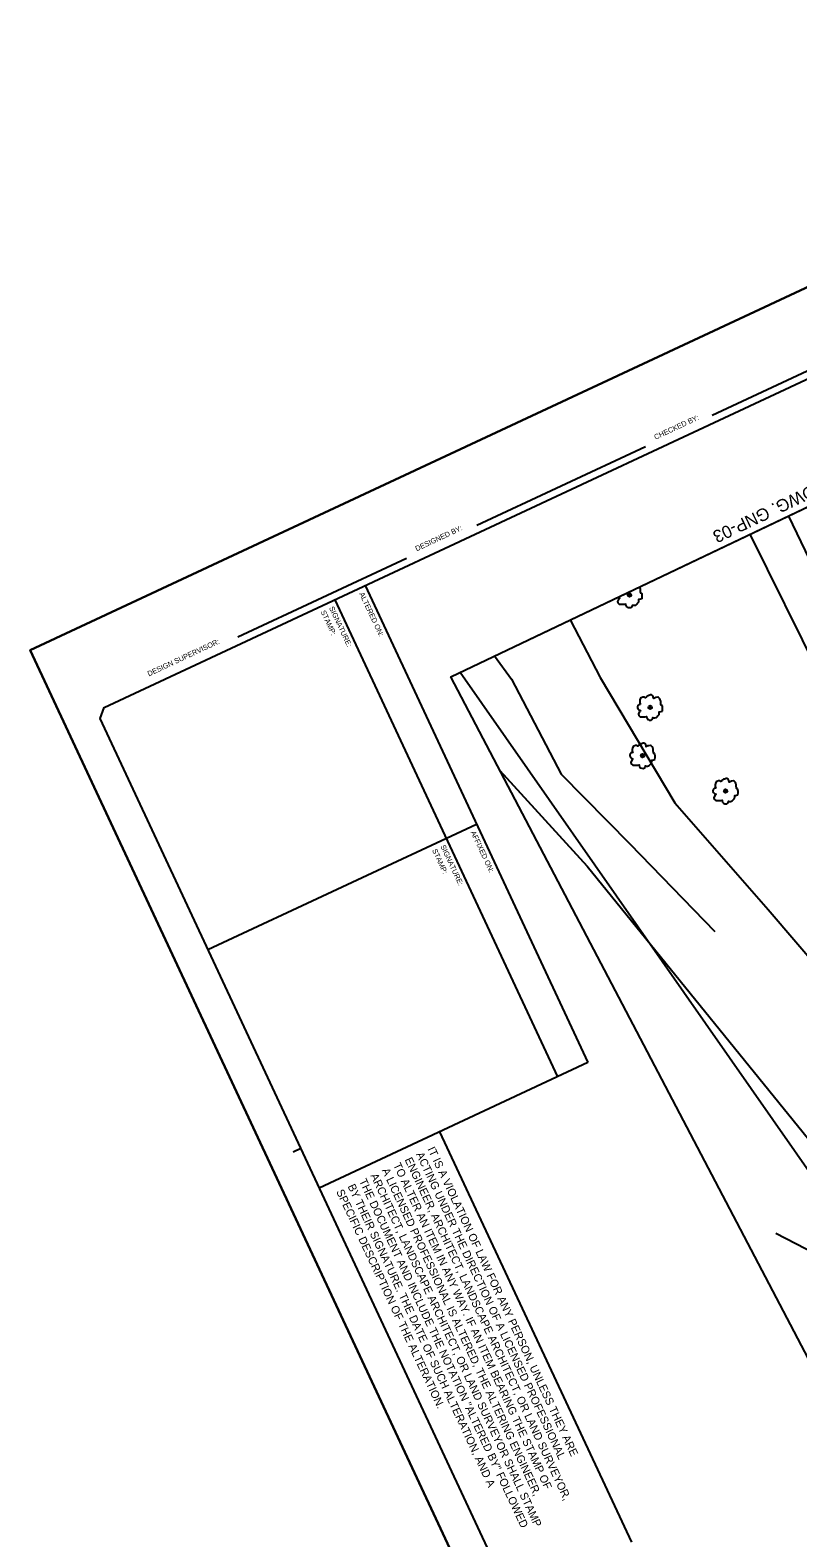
# Model space of a CAD drawing. Extents: x 1040814 to 1041501, y 1126274 to 1127077.
# Drawn here: x 1040814.3 to 1041044.8, y 1126623.9 to 1127076.7 of the extents above; entities that cross this region are included whole.
import ezdxf

# ---------------------------------------------------------------- set-up
doc = ezdxf.new("R2010")
doc.units = 0
for name, color, linetype in [('clip boundary', 7, 'Continuous'), ('LAM', 7, 'Continuous'), ('LAWA', 7, 'Continuous'), ('LELB', 7, 'Continuous'), ('LTD', 7, 'Continuous'), ('MHB', 7, 'Continuous'), ('NML_P', 7, 'Continuous'), ('NML_P_T', 7, 'Continuous'), ('SHEET_BORDER', 7, 'Continuous'), ('SHEET_BORDER_CUT', 7, 'Continuous'), ('SHEET_BORDER_STAMPBOX', 7, 'Continuous'), ('SHEET_BORDER_TEXT', 7, 'Continuous')]:
    doc.layers.add(name, color=color, linetype=linetype)

msp = doc.modelspace()

# ---------------------------------------------------------------- linework, layer by layer
at = {"layer": 'clip boundary'}
for points in [[(1041212.91, 1127076.67), (1041500.71, 1126460.57), (1041102.06, 1126274.35), (1040814.26, 1126890.45)], [(1041214.88, 1127013.05), (1041436.47, 1126509.64), (1041196.3, 1126394.87), (1040940.57, 1126882.48)]]:
    msp.add_lwpolyline(points, close=True, dxfattribs=at)
at = {"layer": 'LAM'}
msp.add_lwpolyline([(1040981.59, 1126825.54), (1040955.31, 1126854.36)], dxfattribs=at)
at = {"layer": 'LAWA'}
for points in [[(1040955.31, 1126854.36), (1040981.59, 1126825.54)], [(1040981.59, 1126825.54), (1041056.77, 1126732.84), (1041104.86, 1126716.99), (1041144.53, 1126704.03), (1041174.4, 1126657.67), (1041200.18, 1126609.9)]]:
    msp.add_lwpolyline(points, dxfattribs=at)
at = {"layer": 'LELB'}
for points in [[(1041041.98, 1126930.75), (1041063.24, 1126886.6), (1041084.03, 1126841.27), (1041108.41, 1126799.02), (1041128.47, 1126753.39), (1041143.12, 1126720.8)], [(1041123.26, 1126726.85), (1041116.78, 1126745.76), (1041096.43, 1126789.68), (1041075.03, 1126831.81), (1041051.47, 1126883.04), (1041030.52, 1126925.29)], [(1040976.45, 1126899.56), (1040985.45, 1126882.27), (1041007.93, 1126844.63)], [(1040953.75, 1126888.75), (1040958.86, 1126881.74), (1040973.79, 1126853.17), (1040994.35, 1126832.28)], [(1041007.93, 1126844.63), (1041035.89, 1126812.55)], [(1040994.35, 1126832.28), (1041019.85, 1126805.94)], [(1041035.89, 1126812.55), (1041051.97, 1126793.82)], [(1041085.87, 1126690.6), (1041038.19, 1126715.23)]]:
    msp.add_lwpolyline(points, dxfattribs=at)
at = {"layer": 'LTD'}
for points in [[(1040997.24, 1126909.45), (1040997.31, 1126909.3), (1040997.43, 1126908.91), (1040997.43, 1126908.35), (1040997.49, 1126907.93), (1040997.46, 1126907.84), (1040997.55, 1126907.72), (1040997.82, 1126907.62)], [(1040997.94, 1126905.85), (1040997.19, 1126905.69), (1040996.98, 1126905.66), (1040997.01, 1126905.22), (1040996.92, 1126904.89), (1040996.8, 1126904.71), (1040996.57, 1126904.44), (1040996.48, 1126904.32), (1040996.18, 1126904.01), (1040996.06, 1126903.92), (1040995.7, 1126903.83), (1040995.27, 1126903.89), (1040995.09, 1126903.92), (1040995.06, 1126903.77), (1040994.91, 1126903.38), (1040994.61, 1126903.2), (1040994.39, 1126903.17), (1040993.97, 1126903.2), (1040993.64, 1126903.32), (1040993.46, 1126903.44), (1040993.34, 1126903.65), (1040993.19, 1126904.07), (1040993.19, 1126904.28), (1040992.78, 1126904.16), (1040992.23, 1126904.13), (1040991.6, 1126904.13), (1040991.3, 1126904.16), (1040990.84, 1126904.53), (1040990.72, 1126905.07), (1040991.08, 1126905.72), (1040991.21, 1126905.9), (1040991.36, 1126906.08), (1040991.14, 1126906.14), (1040990.9, 1126906.27), (1040990.79, 1126906.38)], [(1040994.29, 1126907.02), (1040994.29, 1126907.02), (1040994.29, 1126907.02), (1040994.29, 1126907.04), (1040994.29, 1126907.04), (1040994.29, 1126907.04), (1040994.29, 1126907.05), (1040994.27, 1126907.05), (1040994.27, 1126907.05), (1040994.27, 1126907.05), (1040994.27, 1126907.05), (1040994.27, 1126907.07), (1040994.26, 1126907.07), (1040994.26, 1126907.07), (1040994.26, 1126907.07), (1040994.24, 1126907.07), (1040994.24, 1126907.07), (1040994.24, 1126907.07), (1040994.23, 1126907.07), (1040994.23, 1126907.07), (1040994.23, 1126907.07), (1040994.21, 1126907.07), (1040994.21, 1126907.05), (1040994.21, 1126907.05), (1040994.21, 1126907.05), (1040994.2, 1126907.05), (1040994.2, 1126907.05), (1040994.2, 1126907.04), (1040994.2, 1126907.04), (1040994.2, 1126907.04), (1040994.2, 1126907.02), (1040994.2, 1126907.02), (1040994.2, 1126907.02), (1040994.2, 1126907.01), (1040994.2, 1126907.01), (1040994.2, 1126907.01), (1040994.2, 1126906.99), (1040994.2, 1126906.99), (1040994.21, 1126906.99), (1040994.21, 1126906.99), (1040994.21, 1126906.98), (1040994.21, 1126906.98), (1040994.23, 1126906.98), (1040994.23, 1126906.98), (1040994.23, 1126906.98), (1040994.24, 1126906.98), (1040994.24, 1126906.98), (1040994.24, 1126906.98), (1040994.26, 1126906.98), (1040994.26, 1126906.98), (1040994.26, 1126906.98), (1040994.27, 1126906.98), (1040994.27, 1126906.98), (1040994.27, 1126906.99), (1040994.27, 1126906.99), (1040994.27, 1126906.99), (1040994.29, 1126906.99), (1040994.29, 1126907.01), (1040994.29, 1126907.01), (1040994.29, 1126907.01), (1040994.29, 1126907.02)], [(1040997.82, 1126907.62), (1040997.92, 1126907.32), (1040997.98, 1126906.9), (1040997.98, 1126906.42), (1040997.94, 1126905.85)], [(1040997.6, 1126874.11), (1040997.14, 1126874.17), (1040996.78, 1126873.87), (1040996.66, 1126873.47), (1040996.66, 1126873.17), (1040996.78, 1126872.87), (1040997.11, 1126872.53), (1040997.36, 1126872.41), (1040997.57, 1126872.35), (1040997.42, 1126872.17), (1040997.3, 1126871.99), (1040996.93, 1126871.34), (1040997.05, 1126870.8), (1040997.51, 1126870.43), (1040997.81, 1126870.4), (1040998.44, 1126870.4), (1040998.99, 1126870.43), (1040999.4, 1126870.55), (1040999.4, 1126870.34), (1040999.55, 1126869.92), (1040999.67, 1126869.71), (1040999.85, 1126869.59), (1041000.18, 1126869.47), (1041000.61, 1126869.44), (1041000.82, 1126869.47), (1041001.12, 1126869.65), (1041001.27, 1126870.04), (1041001.3, 1126870.19), (1041001.48, 1126870.16), (1041001.91, 1126870.1), (1041002.27, 1126870.19), (1041002.39, 1126870.28), (1041002.69, 1126870.58), (1041002.78, 1126870.71), (1041003.01, 1126870.98), (1041003.13, 1126871.16), (1041003.22, 1126871.49), (1041003.19, 1126871.93), (1041003.4, 1126871.96), (1041004.15, 1126872.12)], [(1041004.03, 1126873.89), (1041003.77, 1126873.99), (1041003.68, 1126874.11), (1041003.71, 1126874.2), (1041003.65, 1126874.62), (1041003.65, 1126875.18), (1041003.52, 1126875.57), (1041003.37, 1126875.88), (1041003.01, 1126876.24), (1041002.74, 1126876.3), (1041002.21, 1126876.24), (1041002, 1126876.18), (1041001.6, 1126875.97), (1041001.54, 1126875.94), (1041001.48, 1126876.15), (1041001.42, 1126876.48), (1041001.21, 1126876.78), (1041001, 1126876.93), (1041000.82, 1126877.02), (1041000.58, 1126877.02), (1041000.4, 1126876.93), (1041000.09, 1126876.84), (1040999.85, 1126876.78), (1040999.55, 1126876.6), (1040999.4, 1126876.42), (1040998.96, 1126876.15), (1040998.75, 1126876.33), (1040998.32, 1126876.33), (1040997.81, 1126876.15), (1040997.6, 1126876), (1040997.39, 1126875.53), (1040997.33, 1126875.07), (1040997.33, 1126874.65), (1040997.45, 1126874.35), (1040997.6, 1126874.11)], [(1041000.5, 1126873.29), (1041000.5, 1126873.29), (1041000.5, 1126873.29), (1041000.5, 1126873.31), (1041000.5, 1126873.31), (1041000.5, 1126873.31), (1041000.5, 1126873.32), (1041000.49, 1126873.32), (1041000.49, 1126873.32), (1041000.49, 1126873.32), (1041000.49, 1126873.32), (1041000.49, 1126873.34), (1041000.47, 1126873.34), (1041000.47, 1126873.34), (1041000.47, 1126873.34), (1041000.46, 1126873.34), (1041000.46, 1126873.34), (1041000.46, 1126873.34), (1041000.44, 1126873.34), (1041000.44, 1126873.34), (1041000.44, 1126873.34), (1041000.43, 1126873.34), (1041000.43, 1126873.32), (1041000.43, 1126873.32), (1041000.43, 1126873.32), (1041000.41, 1126873.32), (1041000.41, 1126873.32), (1041000.41, 1126873.31), (1041000.41, 1126873.31), (1041000.41, 1126873.31), (1041000.41, 1126873.29), (1041000.41, 1126873.29), (1041000.41, 1126873.29), (1041000.41, 1126873.28), (1041000.41, 1126873.28), (1041000.41, 1126873.28), (1041000.41, 1126873.26), (1041000.41, 1126873.26), (1041000.43, 1126873.26), (1041000.43, 1126873.26), (1041000.43, 1126873.25), (1041000.43, 1126873.25), (1041000.44, 1126873.25), (1041000.44, 1126873.25), (1041000.44, 1126873.25), (1041000.46, 1126873.25), (1041000.46, 1126873.25), (1041000.46, 1126873.25), (1041000.47, 1126873.25), (1041000.47, 1126873.25), (1041000.47, 1126873.25), (1041000.49, 1126873.25), (1041000.49, 1126873.25), (1041000.49, 1126873.26), (1041000.49, 1126873.26), (1041000.49, 1126873.26), (1041000.5, 1126873.26), (1041000.5, 1126873.28), (1041000.5, 1126873.28), (1041000.5, 1126873.28), (1041000.5, 1126873.29)], [(1041004.15, 1126872.12), (1041004.19, 1126872.69), (1041004.19, 1126873.17), (1041004.13, 1126873.59), (1041004.03, 1126873.89)], [(1040995.34, 1126859.62), (1040994.89, 1126859.68), (1040994.52, 1126859.37), (1040994.4, 1126858.98), (1040994.4, 1126858.68), (1040994.52, 1126858.38), (1040994.86, 1126858.04), (1040995.1, 1126857.92), (1040995.31, 1126857.86), (1040995.16, 1126857.68), (1040995.04, 1126857.5), (1040994.68, 1126856.85), (1040994.8, 1126856.31), (1040995.25, 1126855.94), (1040995.55, 1126855.91), (1040996.19, 1126855.91), (1040996.73, 1126855.94), (1040997.14, 1126856.06), (1040997.14, 1126855.85), (1040997.29, 1126855.43), (1040997.41, 1126855.22), (1040997.59, 1126855.1), (1040997.93, 1126854.98), (1040998.35, 1126854.95), (1040998.56, 1126854.98), (1040998.86, 1126855.16), (1040999.01, 1126855.55), (1040999.04, 1126855.7), (1040999.23, 1126855.67), (1040999.65, 1126855.61), (1041000.01, 1126855.7), (1041000.13, 1126855.79), (1041000.44, 1126856.09), (1041000.53, 1126856.22), (1041000.75, 1126856.49), (1041000.87, 1126856.67), (1041000.96, 1126857), (1041000.93, 1126857.44), (1041001.15, 1126857.47), (1041001.89, 1126857.63)], [(1041001.77, 1126859.4), (1041001.51, 1126859.5), (1041001.42, 1126859.62), (1041001.45, 1126859.71), (1041001.39, 1126860.13), (1041001.39, 1126860.69), (1041001.27, 1126861.08), (1041001.12, 1126861.39), (1041000.75, 1126861.75), (1041000.48, 1126861.81), (1040999.95, 1126861.75), (1040999.74, 1126861.69), (1040999.35, 1126861.48), (1040999.29, 1126861.45), (1040999.23, 1126861.66), (1040999.17, 1126861.99), (1040998.95, 1126862.29), (1040998.74, 1126862.44), (1040998.56, 1126862.53), (1040998.32, 1126862.53), (1040998.14, 1126862.44), (1040997.84, 1126862.35), (1040997.59, 1126862.29), (1040997.29, 1126862.11), (1040997.14, 1126861.93), (1040996.7, 1126861.66), (1040996.49, 1126861.84), (1040996.07, 1126861.84), (1040995.55, 1126861.66), (1040995.34, 1126861.51), (1040995.13, 1126861.04), (1040995.07, 1126860.58), (1040995.07, 1126860.16), (1040995.19, 1126859.86), (1040995.34, 1126859.62)], [(1041001.89, 1126857.63), (1041001.93, 1126858.2), (1041001.93, 1126858.68), (1041001.87, 1126859.1), (1041001.77, 1126859.4)], [(1040998.24, 1126858.8), (1040998.24, 1126858.8), (1040998.24, 1126858.8), (1040998.24, 1126858.82), (1040998.24, 1126858.82), (1040998.24, 1126858.82), (1040998.24, 1126858.83), (1040998.23, 1126858.83), (1040998.23, 1126858.83), (1040998.23, 1126858.83), (1040998.23, 1126858.83), (1040998.23, 1126858.85), (1040998.21, 1126858.85), (1040998.21, 1126858.85), (1040998.21, 1126858.85), (1040998.2, 1126858.85), (1040998.2, 1126858.85), (1040998.2, 1126858.85), (1040998.18, 1126858.85), (1040998.18, 1126858.85), (1040998.18, 1126858.85), (1040998.17, 1126858.85), (1040998.17, 1126858.83), (1040998.17, 1126858.83), (1040998.17, 1126858.83), (1040998.15, 1126858.83), (1040998.15, 1126858.83), (1040998.15, 1126858.82), (1040998.15, 1126858.82), (1040998.15, 1126858.82), (1040998.15, 1126858.8), (1040998.15, 1126858.8), (1040998.15, 1126858.8), (1040998.15, 1126858.79), (1040998.15, 1126858.79), (1040998.15, 1126858.79), (1040998.15, 1126858.77), (1040998.15, 1126858.77), (1040998.17, 1126858.77), (1040998.17, 1126858.77), (1040998.17, 1126858.76), (1040998.17, 1126858.76), (1040998.18, 1126858.76), (1040998.18, 1126858.76), (1040998.18, 1126858.76), (1040998.2, 1126858.76), (1040998.2, 1126858.76), (1040998.2, 1126858.76), (1040998.21, 1126858.76), (1040998.21, 1126858.76), (1040998.21, 1126858.76), (1040998.23, 1126858.76), (1040998.23, 1126858.76), (1040998.23, 1126858.77), (1040998.23, 1126858.77), (1040998.23, 1126858.77), (1040998.24, 1126858.77), (1040998.24, 1126858.79), (1040998.24, 1126858.79), (1040998.24, 1126858.79), (1040998.24, 1126858.8)], [(1041026.72, 1126848.77), (1041026.45, 1126848.87), (1041026.36, 1126848.99), (1041026.39, 1126849.08), (1041026.33, 1126849.51), (1041026.33, 1126850.06), (1041026.21, 1126850.46), (1041026.06, 1126850.76), (1041025.69, 1126851.12), (1041025.42, 1126851.18), (1041024.89, 1126851.12), (1041024.68, 1126851.06), (1041024.29, 1126850.85), (1041024.23, 1126850.82), (1041024.17, 1126851.03), (1041024.11, 1126851.36), (1041023.9, 1126851.67), (1041023.68, 1126851.82), (1041023.5, 1126851.91), (1041023.26, 1126851.91), (1041023.08, 1126851.82), (1041022.78, 1126851.73), (1041022.53, 1126851.67), (1041022.23, 1126851.49), (1041022.08, 1126851.3), (1041021.64, 1126851.03), (1041021.43, 1126851.21), (1041021.01, 1126851.21), (1041020.49, 1126851.03), (1041020.28, 1126850.88), (1041020.07, 1126850.41), (1041020.01, 1126849.96), (1041020.01, 1126849.54), (1041020.13, 1126849.23), (1041020.28, 1126848.99)], [(1041020.28, 1126848.99), (1041019.83, 1126849.05), (1041019.47, 1126848.75), (1041019.34, 1126848.36), (1041019.34, 1126848.05), (1041019.47, 1126847.75), (1041019.8, 1126847.42), (1041020.04, 1126847.3), (1041020.25, 1126847.24), (1041020.1, 1126847.06), (1041019.98, 1126846.87), (1041019.62, 1126846.22), (1041019.74, 1126845.68), (1041020.19, 1126845.32), (1041020.49, 1126845.29), (1041021.13, 1126845.29), (1041021.67, 1126845.32), (1041022.08, 1126845.44), (1041022.08, 1126845.23), (1041022.23, 1126844.8), (1041022.35, 1126844.59), (1041022.53, 1126844.47), (1041022.87, 1126844.35), (1041023.29, 1126844.32), (1041023.5, 1126844.35), (1041023.8, 1126844.53), (1041023.96, 1126844.92), (1041023.99, 1126845.08), (1041024.17, 1126845.05), (1041024.59, 1126844.99), (1041024.95, 1126845.08), (1041025.07, 1126845.17), (1041025.38, 1126845.47), (1041025.47, 1126845.59), (1041025.69, 1126845.86), (1041025.82, 1126846.04), (1041025.91, 1126846.38), (1041025.88, 1126846.81), (1041026.09, 1126846.84), (1041026.83, 1126847)], [(1041023.18, 1126848.18), (1041023.18, 1126848.18), (1041023.18, 1126848.18), (1041023.18, 1126848.19), (1041023.18, 1126848.19), (1041023.18, 1126848.19), (1041023.18, 1126848.21), (1041023.17, 1126848.21), (1041023.17, 1126848.21), (1041023.17, 1126848.21), (1041023.17, 1126848.21), (1041023.17, 1126848.22), (1041023.15, 1126848.22), (1041023.15, 1126848.22), (1041023.15, 1126848.22), (1041023.14, 1126848.22), (1041023.14, 1126848.22), (1041023.14, 1126848.22), (1041023.12, 1126848.22), (1041023.12, 1126848.22), (1041023.12, 1126848.22), (1041023.11, 1126848.22), (1041023.11, 1126848.21), (1041023.11, 1126848.21), (1041023.11, 1126848.21), (1041023.09, 1126848.21), (1041023.09, 1126848.21), (1041023.09, 1126848.19), (1041023.09, 1126848.19), (1041023.09, 1126848.19), (1041023.09, 1126848.18), (1041023.09, 1126848.18), (1041023.09, 1126848.18), (1041023.09, 1126848.16), (1041023.09, 1126848.16), (1041023.09, 1126848.16), (1041023.09, 1126848.14), (1041023.09, 1126848.14), (1041023.11, 1126848.14), (1041023.11, 1126848.14), (1041023.11, 1126848.13), (1041023.11, 1126848.13), (1041023.12, 1126848.13), (1041023.12, 1126848.13), (1041023.12, 1126848.13), (1041023.14, 1126848.13), (1041023.14, 1126848.13), (1041023.14, 1126848.13), (1041023.15, 1126848.13), (1041023.15, 1126848.13), (1041023.15, 1126848.13), (1041023.17, 1126848.13), (1041023.17, 1126848.13), (1041023.17, 1126848.14), (1041023.17, 1126848.14), (1041023.17, 1126848.14), (1041023.18, 1126848.14), (1041023.18, 1126848.16), (1041023.18, 1126848.16), (1041023.18, 1126848.16), (1041023.18, 1126848.18)], [(1041026.83, 1126847), (1041026.87, 1126847.57), (1041026.87, 1126848.05), (1041026.81, 1126848.48), (1041026.72, 1126848.77)]]:
    msp.add_lwpolyline(points, dxfattribs=at)
for centre in [(1040994.24, 1126907.02), (1041000.46, 1126873.29), (1040998.2, 1126858.8), (1041023.14, 1126848.18)]:
    msp.add_circle(centre, 0.533, dxfattribs=at)
at = {"layer": 'MHB'}
msp.add_lwpolyline([(1040943.43, 1126883.84), (1041077.77, 1126691.61), (1041170.82, 1126625.52), (1041174.77, 1126621.37)], dxfattribs=at)
at = {"layer": 'NML_P'}
msp.add_line((1040940.57, 1126882.48), (1041214.88, 1127013.05), dxfattribs=at)
at = {"layer": 'SHEET_BORDER'}
for p, q in [((1041019.1, 1126961), (1041069.77, 1126984.67)), ((1040948.38, 1126927.97), (1040999.04, 1126951.63)), ((1040876.65, 1126894.46), (1040927.25, 1126918.1)), ((1040895.55, 1126740.79), (1040893.29, 1126739.73))]:
    msp.add_line(p, q, dxfattribs=at)
msp.add_lwpolyline([(1041103.08, 1126302.42), (1041099.76, 1126303.63), (1040835.24, 1126869.9), (1040836.45, 1126873.22), (1041211.88, 1127048.6), (1041215.2, 1127047.39), (1041479.72, 1126481.12), (1041478.52, 1126477.8)], close=True, dxfattribs=at)
at = {"layer": 'SHEET_BORDER_CUT'}
msp.add_lwpolyline([(1040814.26, 1126890.45), (1041102.06, 1126274.35), (1041500.71, 1126460.57), (1041212.91, 1127076.67)], close=True, dxfattribs=at)
msp.add_lwpolyline([(1040817.25, 1126884.04), (1040814.26, 1126890.45), (1040820.67, 1126893.44)], dxfattribs=at)
at = {"layer": 'SHEET_BORDER_STAMPBOX'}
for p, q in [((1040914.88, 1126909.85), (1040981.8, 1126766.59)), ((1040972.74, 1126762.36), (1040905.82, 1126905.62)), ((1040867.64, 1126800.53), (1040948.34, 1126838.22)), ((1040981.8, 1126766.59), (1040901.11, 1126728.9)), ((1040994.93, 1126622.55), (1040937.35, 1126745.83))]:
    msp.add_line(p, q, dxfattribs=at)

# ---------------------------------------------------------------- texts
at = {"layer": 'NML_P_T'}
msp.add_text('MATCHLINE STA. 13+00 - SEE DWG. GNP-03', height=3.744, rotation=205.4556, dxfattribs=at).set_placement((1041114.51, 1126971.4))
at = {"layer": 'SHEET_BORDER_STAMPBOX'}
for s, height, p in [('ALTERED ON:', 1.5625, (1040913.05, 1126907.41)), ('STAMP:', 1.562, (1040901.47, 1126902)), ('SIGNATURE:', 1.562, (1040903.98, 1126903.18)), ('SIGNATURE:', 1.562, (1040937.45, 1126831.54)), ('AFFIXED ON:', 1.5625, (1040946.51, 1126835.78)), ('STAMP:', 1.562, (1040934.93, 1126830.37)), ('IT IS A VIOLATION OF LAW FOR ANY PERSON, UNLESS THEY ARE ', 2.4, (1040933.53, 1126740.66)), ('TO ALTER AN ITEM IN ANY WAY. IF AN ITEM BEARING THE STAMP OF ', 2.4, (1040923.25, 1126735.86)), ('ENGINEER, ARCHITECT, LANDSCAPE ARCHITECT, OR LAND SURVEYOR, ', 2.4, (1040926.68, 1126737.46)), ('ACTING UNDER THE DIRECTION OF A LICENSED PROFESSIONAL ', 2.4, (1040930.11, 1126739.06)), ('ARCHITECT, LANDSCAPE ARCHITECT, OR LAND SURVEYOR SHALL STAMP ', 2.4, (1040916.4, 1126732.66)), ('A LICENSED PROFESSIONAL IS ALTERED, THE ALTERING ENGINEER, ', 2.4, (1040919.83, 1126734.26)), ('SPECIFIC DESCRIPTION OF THE ALTERATION.', 2.4, (1040906.12, 1126727.86)), ('BY THEIR SIGNATURE. THE DATE OF SUCH ALTERATION, AND A ', 2.4, (1040909.55, 1126729.46)), ('THE DOCUMENT AND INCLUDE THE NOTATION "ALTERED BY" FOLLOWED ', 2.4, (1040912.98, 1126731.06))]:
    msp.add_text(s, height=height, rotation=295.0387, dxfattribs=at).set_placement(p)
at = {"layer": 'SHEET_BORDER_TEXT'}
for s, p in [('CHECKED BY:', (1041002.09, 1126953.63)), ('DESIGNED BY:', (1040930.35, 1126920.12)), ('DESIGN SUPERVISOR:', (1040849.93, 1126882.55))]:
    msp.add_text(s, height=1.5625, rotation=25.0387, dxfattribs=at).set_placement(p)

doc.saveas('drawing.dxf')
